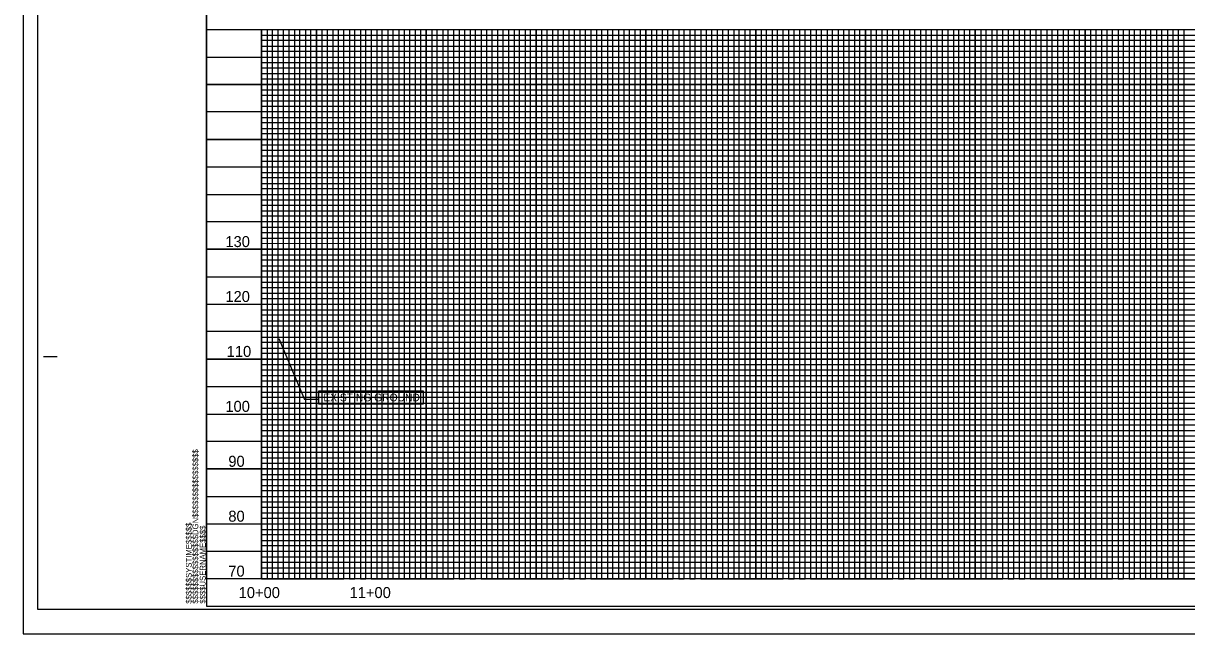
# Model space of a CAD drawing. Extents: x 10070 to 15319, y 8517 to 10343.
# Drawn here: x 13208 to 14267, y 8517 to 9072 of the extents above; entities that cross this region are included whole.
import ezdxf

# ---------------------------------------------------------------- set-up
doc = ezdxf.new("R2010")
doc.units = 0
for name, color, linetype in [('Exist Vertical Profile Horizontal Axis Label Major', 7, 'Continuous'), ('Exist Vertical Profile Vertical Axis Label', 7, 'Continuous'), ('Prop Grid Mask', 7, 'Continuous'), ('Prop VPI Label', 7, 'Continuous'), ('Scratch_Level_3', 7, 'Continuous'), ('Sheet Cutting Line CELL', 7, 'Continuous'), ('Sheet DOT Grid CELL', 7, 'Continuous'), ('Sheet Layout Profile Border Port 2', 7, 'Continuous'), ('Sheet Plot Border Inside CELL', 7, 'Continuous'), ('Sheet Plot Border Outside CELL', 7, 'Continuous'), ('Sheet Profile CELL', 7, 'Continuous'), ('Sheet Profile Grid Major CELL', 7, 'Continuous'), ('Sheet Profile Grid Middle CELL', 7, 'Continuous'), ('Sheet Profile Grid Minor CELL', 7, 'Continuous')]:
    doc.layers.add(name, color=color, linetype=linetype)

msp = doc.modelspace()

# ---------------------------------------------------------------- linework, layer by layer
at = {"layer": 'Prop Grid Mask'}
msp.add_lwpolyline([(13477, 8725.7), (13477, 8737.9), (13572.1, 8737.9), (13572.1, 8725.7)], close=True, dxfattribs=at)
at = {"layer": 'Prop VPI Label'}
for p in [(13440.7, 8785.6), (13477, 8729.8)]:
    msp.add_line(p, (13464.1, 8729.8), dxfattribs=at)
at = {"layer": 'Scratch_Level_3'}
msp.add_lwpolyline([(13374.9, 9591.7), (14824.9, 9591.7), (14824.9, 8566.7), (13374.9, 8566.7)], close=True, dxfattribs=at)
at = {"layer": 'Sheet Cutting Line CELL'}
for p, q in [((13207.9, 9616.7), (13207.9, 8516.7)), ((13207.9, 8516.7), (14891.9, 8516.7))]:
    msp.add_line(p, q, dxfattribs=at)
at = {"layer": 'Sheet DOT Grid CELL'}
for p, q in [((13374.9, 9066.7), (14874.8, 9066.7)), ((13424.9, 9066.7), (13424.9, 8566.7)), ((13474.9, 9066.7), (13474.9, 8566.7)), ((13524.9, 9066.7), (13524.9, 8566.7)), ((13574.9, 9066.7), (13574.9, 8566.7)), ((13624.9, 9066.7), (13624.9, 8566.7)), ((13674.9, 9066.7), (13674.9, 8566.7)), ((13724.9, 9066.7), (13724.9, 8566.7)), ((13774.9, 9066.7), (13774.9, 8566.7)), ((13824.9, 9066.7), (13824.9, 8566.7)), ((13874.9, 9066.7), (13874.9, 8566.7)), ((13924.9, 9066.7), (13924.9, 8566.7)), ((13974.9, 9066.7), (13974.9, 8566.7)), ((14024.9, 9066.7), (14024.9, 8566.7)), ((14074.9, 9066.7), (14074.9, 8566.7)), ((14124.9, 9066.7), (14124.9, 8566.7)), ((14174.9, 9066.7), (14174.9, 8566.7)), ((14224.9, 9066.7), (14224.9, 8566.7)), ((13374.9, 9016.7), (14874.8, 9016.7)), ((13374.9, 8966.7), (14874.8, 8966.7)), ((13374.9, 8916.7), (14874.8, 8916.7)), ((13374.9, 8866.7), (14874.8, 8866.7)), ((13374.9, 8816.7), (14874.8, 8816.7)), ((13374.9, 8766.7), (14874.8, 8766.7)), ((13374.9, 8716.7), (14874.8, 8716.7)), ((13374.9, 8666.7), (14874.8, 8666.7)), ((13374.9, 8616.7), (14874.8, 8616.7))]:
    msp.add_line(p, q, dxfattribs=at)
at = {"layer": 'Sheet Layout Profile Border Port 2'}
msp.add_lwpolyline([(13424.9, 9066.7), (14824.9, 9066.7), (14824.9, 8566.7), (13424.9, 8566.7)], close=True, dxfattribs=at)
at = {"layer": 'Sheet Plot Border Inside CELL'}
msp.add_lwpolyline([(13220.9, 8539.2), (14887.4, 8539.2), (14887.4, 9594.3), (13220.9, 9594.3)], close=True, dxfattribs=at)
at = {"layer": 'Sheet Plot Border Outside CELL'}
msp.add_lwpolyline([(13207.9, 8516.7), (14891.9, 8516.7), (14891.9, 9616.7), (13207.9, 9616.7)], close=True, dxfattribs=at)
at = {"layer": 'Sheet Profile CELL'}
for p, q in [((13374.9, 9066.7), (14874.9, 9066.7)), ((13226.4, 8769.2), (13238.9, 8769.2)), ((14874.9, 8566.7), (13374.9, 8566.7)), ((13374.9, 8541.7), (14874.9, 8541.7)), ((13374.9, 8541.7), (13374.9, 8541.7)), ((13374.9, 8541.7), (13374.9, 8541.7)), ((13374.9, 8541.7), (13374.9, 8541.7)), ((13374.9, 8541.7), (13374.9, 8541.7)), ((13374.9, 8541.7), (13374.9, 8541.7)), ((13374.9, 8541.7), (13374.9, 8541.7)), ((13374.9, 8541.7), (13374.9, 8541.7))]:
    msp.add_line(p, q, dxfattribs=at)
msp.add_lwpolyline([(14874.9, 9591.7), (13374.9, 9591.7), (13374.9, 8541.7), (14874.9, 8541.7)], close=True, dxfattribs=at)
msp.add_lwpolyline([(13412.4, 8541.7), (13412.4, 8541.7)], dxfattribs=at)
at = {"layer": 'Sheet Profile Grid Major CELL'}
for p, q in [((13874.9, 9066.7), (13924.9, 9066.7)), ((13974.9, 9066.7), (14024.9, 9066.7)), ((14074.9, 9066.7), (14124.9, 9066.7)), ((14174.9, 9066.7), (14224.9, 9066.7)), ((13374.9, 8566.7), (13374.9, 8566.7))]:
    msp.add_line(p, q, dxfattribs=at)
for points in [[(13424.9, 9066.7), (13424.9, 8566.7), (13474.9, 8566.7), (13474.9, 9066.7), (13524.9, 9066.7), (13524.9, 8566.7), (13574.9, 8566.7), (13574.9, 9066.7), (13624.9, 9066.7), (13624.9, 8566.7), (13674.9, 8566.7), (13674.9, 9066.7), (13724.9, 9066.7), (13724.9, 8566.7), (13774.9, 8566.7), (13774.9, 9066.7), (13824.9, 9066.7), (13824.9, 8566.7), (13874.9, 8566.7), (13874.9, 9066.7), (13924.9, 9066.7), (13924.9, 8566.7), (13974.9, 8566.7), (13974.9, 9066.7), (14024.9, 9066.7), (14024.9, 8566.7), (14074.9, 8566.7), (14074.9, 9066.7), (14124.9, 9066.7), (14124.9, 8566.7), (14174.9, 8566.7), (14174.9, 9066.7), (14224.9, 9066.7), (14224.9, 8566.7), (14274.9, 8566.7)], [(14874.9, 9016.7), (13374.9, 9016.7)], [(14874.9, 8966.7), (13374.9, 8966.7), (13374.9, 8916.7), (14874.9, 8916.7)], [(14874.9, 8866.7), (13374.9, 8866.7), (13374.9, 8816.7), (14874.9, 8816.7)], [(14874.9, 8766.7), (13374.9, 8766.7), (13374.9, 8716.7), (14874.9, 8716.7)], [(14874.9, 8666.7), (13374.9, 8666.7), (13374.9, 8666.7), (13374.9, 8616.7), (14874.9, 8616.7)], [(14874.9, 8566.7), (13374.9, 8566.7)]]:
    msp.add_lwpolyline(points, dxfattribs=at)
at = {"layer": 'Sheet Profile Grid Middle CELL'}
for points in [[(13399.9, 9066.7), (13449.9, 9066.7), (13449.9, 8566.7), (13499.9, 8566.7), (13499.9, 9066.7), (13549.9, 9066.7), (13549.9, 8566.7), (13599.9, 8566.7), (13599.9, 9066.7), (13649.9, 9066.7), (13649.9, 8566.7), (13699.9, 8566.7), (13699.9, 9066.7), (13749.9, 9066.7), (13749.9, 8566.7), (13799.9, 8566.7), (13799.9, 9066.7), (13849.9, 9066.7), (13849.9, 8566.7), (13899.9, 8566.7), (13899.9, 9066.7), (13949.9, 9066.7), (13949.9, 8566.7), (13999.9, 8566.7), (13999.9, 8566.7), (13999.9, 9066.7), (14049.9, 9066.7), (14049.9, 8566.7), (14099.9, 8566.7), (14099.9, 9066.7), (14149.9, 9066.7), (14149.9, 8566.7), (14199.9, 8566.7), (14199.9, 9066.7), (14249.9, 9066.7), (14249.9, 8566.7), (14299.9, 8566.7)], [(13374.9, 9041.7), (14874.9, 9041.7)], [(14874.9, 8991.7), (13374.9, 8991.7), (13374.9, 8941.7), (14874.9, 8941.7)], [(14874.9, 8891.7), (13374.9, 8891.7), (13374.9, 8841.7), (14874.9, 8841.7)], [(14874.9, 8791.7), (13374.9, 8791.7), (13374.9, 8741.7), (14874.9, 8741.7)], [(14874.9, 8691.7), (13374.9, 8691.7), (13374.9, 8641.7), (14874.9, 8641.7)], [(14874.9, 8591.7), (13374.9, 8591.7)]]:
    msp.add_lwpolyline(points, dxfattribs=at)
at = {"layer": 'Sheet Profile Grid Minor CELL'}
for p, q in [((13424.9, 9061.7), (14824.9, 9061.7)), ((14824.9, 9056.7), (13424.9, 9056.7)), ((13424.9, 9051.7), (14824.9, 9051.7)), ((14824.9, 9046.7), (13424.9, 9046.7)), ((13424.9, 9036.7), (14824.9, 9036.7)), ((14824.9, 9031.7), (13424.9, 9031.7)), ((13424.9, 9026.7), (14824.9, 9026.7)), ((14824.9, 9021.7), (13424.9, 9021.7)), ((13424.9, 9011.7), (14824.9, 9011.7)), ((14824.9, 9006.7), (13424.9, 9006.7)), ((13424.9, 9001.7), (14824.9, 9001.7)), ((14824.9, 8996.7), (13424.9, 8996.7)), ((13424.9, 8986.7), (14824.9, 8986.7)), ((14824.9, 8981.7), (13424.9, 8981.7)), ((13424.9, 8976.7), (14824.9, 8976.7)), ((14824.9, 8971.7), (13424.9, 8971.7)), ((13424.9, 8961.7), (14824.9, 8961.7)), ((14824.9, 8956.7), (13424.9, 8956.7)), ((13424.9, 8951.7), (14824.9, 8951.7)), ((14824.9, 8946.7), (13424.9, 8946.7)), ((13424.9, 8936.7), (14824.9, 8936.7)), ((14824.9, 8931.7), (13424.9, 8931.7)), ((13424.9, 8926.7), (14824.9, 8926.7)), ((14824.9, 8921.7), (13424.9, 8921.7)), ((13424.9, 8911.7), (14824.9, 8911.7)), ((14824.9, 8906.7), (13424.9, 8906.7)), ((13424.9, 8901.7), (14824.9, 8901.7)), ((14824.9, 8896.7), (13424.9, 8896.7)), ((13424.9, 8886.7), (14824.9, 8886.7)), ((14824.9, 8881.7), (13424.9, 8881.7)), ((13424.9, 8876.7), (14824.9, 8876.7)), ((14824.9, 8871.7), (13424.9, 8871.9)), ((13424.9, 8861.7), (14824.9, 8861.7)), ((14824.9, 8856.7), (13424.9, 8856.7)), ((13424.9, 8851.7), (14824.9, 8851.7)), ((14824.9, 8846.7), (13424.9, 8846.7)), ((13424.9, 8836.7), (14824.9, 8836.7)), ((14824.9, 8831.7), (13424.9, 8831.7)), ((13424.9, 8826.7), (14824.9, 8826.7)), ((14824.9, 8821.7), (13424.9, 8821.7)), ((13424.9, 8811.7), (14824.9, 8811.7)), ((14824.9, 8806.7), (13424.9, 8806.7)), ((13424.9, 8801.7), (14824.9, 8801.7)), ((14824.9, 8796.7), (13424.9, 8796.7)), ((13424.9, 8786.7), (14824.9, 8786.7)), ((14824.9, 8781.7), (13424.9, 8781.7)), ((13424.9, 8776.7), (14824.9, 8776.7)), ((14824.9, 8771.7), (13424.9, 8771.7)), ((13424.9, 8761.7), (14824.9, 8761.7)), ((14824.9, 8756.7), (13424.9, 8756.7)), ((13424.9, 8751.7), (14824.9, 8751.7)), ((14824.9, 8746.7), (13424.9, 8746.7)), ((13424.9, 8736.7), (14824.9, 8736.7)), ((14824.9, 8731.7), (13424.9, 8731.7)), ((13424.9, 8726.7), (14824.9, 8726.7)), ((14824.9, 8721.7), (13424.9, 8721.7)), ((13424.9, 8711.7), (14824.9, 8711.7)), ((14824.9, 8706.7), (13424.9, 8706.7)), ((13424.9, 8701.7), (14824.9, 8701.7)), ((14824.9, 8696.7), (13424.9, 8696.7)), ((13424.9, 8686.7), (14824.9, 8686.7)), ((14824.9, 8681.7), (13424.9, 8681.7)), ((13424.9, 8676.7), (14824.9, 8676.7)), ((14824.9, 8671.7), (13424.9, 8671.7)), ((13424.9, 8661.7), (14824.9, 8661.7)), ((14824.9, 8656.7), (13424.9, 8656.7)), ((13424.9, 8651.7), (14824.9, 8651.7)), ((14824.9, 8646.7), (13424.9, 8646.7)), ((13424.9, 8636.7), (14824.9, 8636.7)), ((14824.9, 8631.7), (13424.9, 8631.7)), ((13424.9, 8626.7), (14824.9, 8626.7)), ((14824.9, 8621.7), (13424.9, 8621.7)), ((13424.9, 8611.7), (14824.9, 8611.7)), ((14824.9, 8606.7), (13424.9, 8606.7)), ((13424.9, 8601.7), (14824.9, 8601.7)), ((14824.9, 8596.7), (13424.9, 8596.7)), ((13424.9, 8586.7), (14824.9, 8586.7)), ((14824.9, 8581.7), (13424.9, 8581.7)), ((13424.9, 8576.7), (14824.9, 8576.7)), ((13424.9, 8571.7), (14824.9, 8571.7))]:
    msp.add_line(p, q, dxfattribs=at)
for points in [[(13424.9, 9066.7), (13429.9, 9066.7), (13429.9, 8566.7), (13434.9, 8566.7), (13434.9, 9066.7), (13439.9, 9066.7), (13439.9, 8566.7), (13444.9, 8566.7), (13444.9, 9066.7), (13454.9, 9066.7), (13454.9, 8566.7), (13459.9, 8566.7), (13459.9, 9066.7), (13464.9, 9066.7), (13464.9, 8566.7), (13469.9, 8566.7), (13479.9, 8566.7), (13484.9, 8566.7), (13484.9, 9066.7), (13489.9, 9066.7), (13489.9, 8566.7), (13494.9, 8566.7), (13494.9, 9066.7), (13504.9, 9066.7), (13504.9, 8566.7), (13509.9, 8566.7), (13509.9, 9066.7), (13514.9, 9066.7), (13514.9, 8566.7), (13519.9, 8566.7), (13519.9, 9066.7), (13529.9, 9066.7), (13529.9, 8566.7), (13534.9, 8566.7), (13534.9, 9066.7), (13539.9, 9066.7), (13539.9, 8566.7), (13544.9, 8566.7), (13544.9, 9066.7), (13554.9, 9066.7), (13554.9, 8566.7), (13559.9, 8566.7), (13559.9, 9066.7), (13564.9, 9066.7), (13564.9, 8566.7), (13569.9, 8566.7), (13569.9, 9066.7), (13579.9, 9066.7), (13579.9, 8566.7), (13584.9, 8566.7), (13584.9, 9066.7), (13589.9, 9066.7), (13589.9, 8566.7), (13594.9, 8566.7), (13594.9, 9066.7), (13604.9, 9066.7), (13604.9, 8566.7), (13609.9, 8566.7), (13609.9, 9066.7), (13614.9, 9066.7), (13614.9, 8566.7), (13619.9, 8566.7), (13619.9, 9066.7), (13629.9, 9066.7), (13629.9, 8566.7), (13634.9, 8566.7), (13634.9, 9066.7), (13639.9, 9066.7), (13639.9, 8566.7)], [(13469.9, 8566.7), (13469.9, 9066.7), (13479.9, 9066.7), (13479.9, 8566.7)], [(13639.9, 8566.7), (13644.9, 8566.7), (13644.9, 9066.7), (13654.9, 9066.7), (13654.9, 8566.7), (13659.9, 8566.7), (13659.9, 9066.7), (13664.9, 9066.7), (13664.9, 8566.7), (13669.9, 8566.7), (13669.9, 9066.7), (13679.9, 9066.7), (13679.9, 8566.7), (13684.9, 8566.7), (13684.9, 9066.7), (13689.9, 9066.7), (13689.9, 8566.7), (13694.9, 8566.7), (13694.9, 9066.7), (13704.9, 9066.7), (13704.9, 8566.7), (13709.9, 8566.7), (13709.9, 9066.7), (13714.9, 9066.7), (13714.9, 8566.7), (13719.9, 8566.7), (13719.9, 9066.7), (13729.9, 9066.7), (13729.9, 8566.7), (13734.9, 8566.7), (13734.9, 9066.7), (13739.9, 9066.7), (13739.9, 8566.7), (13744.9, 8566.7), (13744.9, 9066.7), (13754.9, 9066.7), (13754.9, 8566.7), (13759.9, 8566.7), (13759.9, 9066.7), (13764.9, 9066.7), (13764.9, 8566.7), (13769.9, 8566.7), (13769.9, 9066.7), (13779.9, 9066.7), (13779.9, 8566.7), (13784.9, 8566.7), (13784.9, 9066.7), (13789.9, 9066.7), (13789.9, 8566.7), (13794.9, 8566.7), (13794.9, 9066.7), (13804.9, 9066.7), (13804.9, 8566.7), (13809.9, 8566.7), (13809.9, 9066.7), (13814.9, 9066.7), (13814.9, 8566.7), (13819.9, 8566.7), (13819.9, 9066.7), (13829.9, 9066.7), (13829.9, 8566.7), (13834.9, 8566.7), (13834.9, 9066.7), (13839.9, 9066.7), (13839.9, 8566.7), (13844.9, 8566.7), (13844.9, 9066.7), (13854.9, 9066.7), (13854.9, 8566.7), (13859.9, 8566.7), (13859.9, 9066.7), (13864.9, 9066.7), (13864.9, 8566.7), (13869.9, 8566.7), (13869.9, 9066.7), (13879.9, 9066.7), (13879.9, 8566.7), (13884.9, 8566.7), (13884.9, 9066.7), (13889.9, 9066.7), (13889.9, 8566.7), (13894.9, 8566.7), (13894.9, 9066.7), (13904.9, 9066.7), (13904.9, 8566.7), (13909.9, 8566.7), (13909.9, 9066.7), (13914.9, 9066.7), (13914.9, 8566.7), (13919.9, 8566.7), (13919.9, 9066.7), (13929.9, 9066.7), (13929.9, 8566.7), (13934.9, 8566.7), (13934.9, 9066.7), (13939.9, 9066.7), (13939.9, 8566.7), (13944.9, 8566.7), (13944.9, 9066.7), (13954.9, 9066.7)], [(13954.9, 9066.7), (13954.9, 8566.7), (13959.9, 8566.7), (13959.9, 9066.7), (13964.9, 9066.7), (13964.9, 8566.7), (13969.9, 8566.7), (13969.9, 9066.7), (13979.9, 9066.7), (13979.9, 8566.7), (13984.9, 8566.7), (13984.9, 9066.7), (13989.9, 9066.7), (13989.9, 8566.7), (13994.9, 8566.7), (13994.9, 9066.7), (14004.9, 9066.7), (14004.9, 8566.7), (14009.9, 8566.7), (14009.9, 9066.7), (14014.9, 9066.7), (14014.9, 8566.7), (14019.9, 8566.7), (14019.9, 9066.7), (14029.9, 9066.7), (14029.9, 8566.7), (14034.9, 8566.7), (14034.9, 9066.7), (14039.9, 9066.7), (14039.9, 8566.7), (14044.9, 8566.7), (14044.9, 9066.7), (14054.9, 9066.7), (14054.9, 8566.7), (14059.9, 8566.7), (14059.9, 9066.7), (14064.9, 9066.7), (14064.9, 8566.7), (14069.9, 8566.7), (14069.9, 9066.7), (14079.9, 9066.7), (14079.9, 8566.7), (14079.9, 8566.7), (14084.9, 8566.7), (14084.9, 9066.7), (14089.9, 9066.7), (14089.9, 8566.7), (14094.9, 8566.7), (14094.9, 9066.7), (14104.9, 9066.7), (14104.9, 8566.7), (14109.9, 8566.7), (14109.9, 9066.7), (14114.9, 9066.7), (14114.9, 8566.7), (14119.9, 8566.7), (14119.9, 9066.7), (14129.9, 9066.7), (14129.9, 8566.7), (14134.9, 8566.7), (14134.9, 9066.7), (14139.9, 9066.7), (14139.9, 8566.7), (14144.9, 8566.7), (14144.9, 9066.7), (14154.9, 9066.7), (14154.9, 8566.7), (14159.9, 8566.7), (14159.9, 9066.7), (14164.9, 9066.7), (14164.9, 8566.7), (14169.9, 8566.7), (14169.9, 9066.7), (14179.9, 9066.7), (14179.9, 8566.7), (14184.9, 8566.7), (14184.9, 9066.7), (14189.9, 9066.7), (14189.9, 8566.7), (14194.9, 8566.7), (14194.9, 9066.7), (14204.9, 9066.7), (14204.9, 8566.7), (14209.9, 8566.7), (14209.9, 9066.7), (14214.9, 9066.7), (14214.9, 8566.7), (14219.9, 8566.7), (14219.9, 9066.7), (14229.9, 9066.7), (14229.9, 8566.7), (14234.6, 8567.3), (14234.9, 8566.7), (14234.9, 9066.7), (14239.9, 9066.7), (14239.9, 8566.7), (14244.9, 8566.7), (14244.9, 9066.7), (14254.9, 9066.7), (14254.9, 8566.7), (14259.9, 8566.7)], [(14259.9, 8566.7), (14259.9, 9066.7), (14264.9, 9066.7), (14264.9, 8566.7), (14269.9, 8566.7)]]:
    msp.add_lwpolyline(points, dxfattribs=at)

# ---------------------------------------------------------------- texts
at = {"layer": 'Exist Vertical Profile Horizontal Axis Label Major'}
for s, p in [('10+00', (13404.1, 8549.2)), ('11+00', (13505.1, 8549.2))]:
    msp.add_text(s, height=10, dxfattribs=at).set_placement(p)
at = {"layer": 'Exist Vertical Profile Vertical Axis Label'}
for s, p in [('130', (13392, 8868.7)), ('120', (13392, 8818.7)), ('110', (13393.2, 8768.7)), ('100', (13392, 8718.7)), ('90', (13394.7, 8668.7)), ('80', (13394.7, 8618.7)), ('70', (13394.7, 8568.7))]:
    msp.add_text(s, height=10, dxfattribs=at).set_placement(p)
at = {"layer": 'Prop VPI Label'}
msp.add_text('EXISTING GROUND', height=7, rotation=360, dxfattribs=at).set_placement((13481.2, 8728.3))
at = {"layer": 'Sheet Profile CELL'}
for s, p in [('$$$$$$$$$$$$$$$$DGN$$$$$$$$$$$$$$$$', (13367.3, 8544.1)), ('$$$$$$SYSTIME$$$$$', (13361.3, 8544.1)), ('$$$$USERNAME$$$$', (13373.9, 8544.1))]:
    msp.add_text(s, height=5.25, rotation=90, dxfattribs=at).set_placement(p)

doc.saveas('drawing.dxf')
